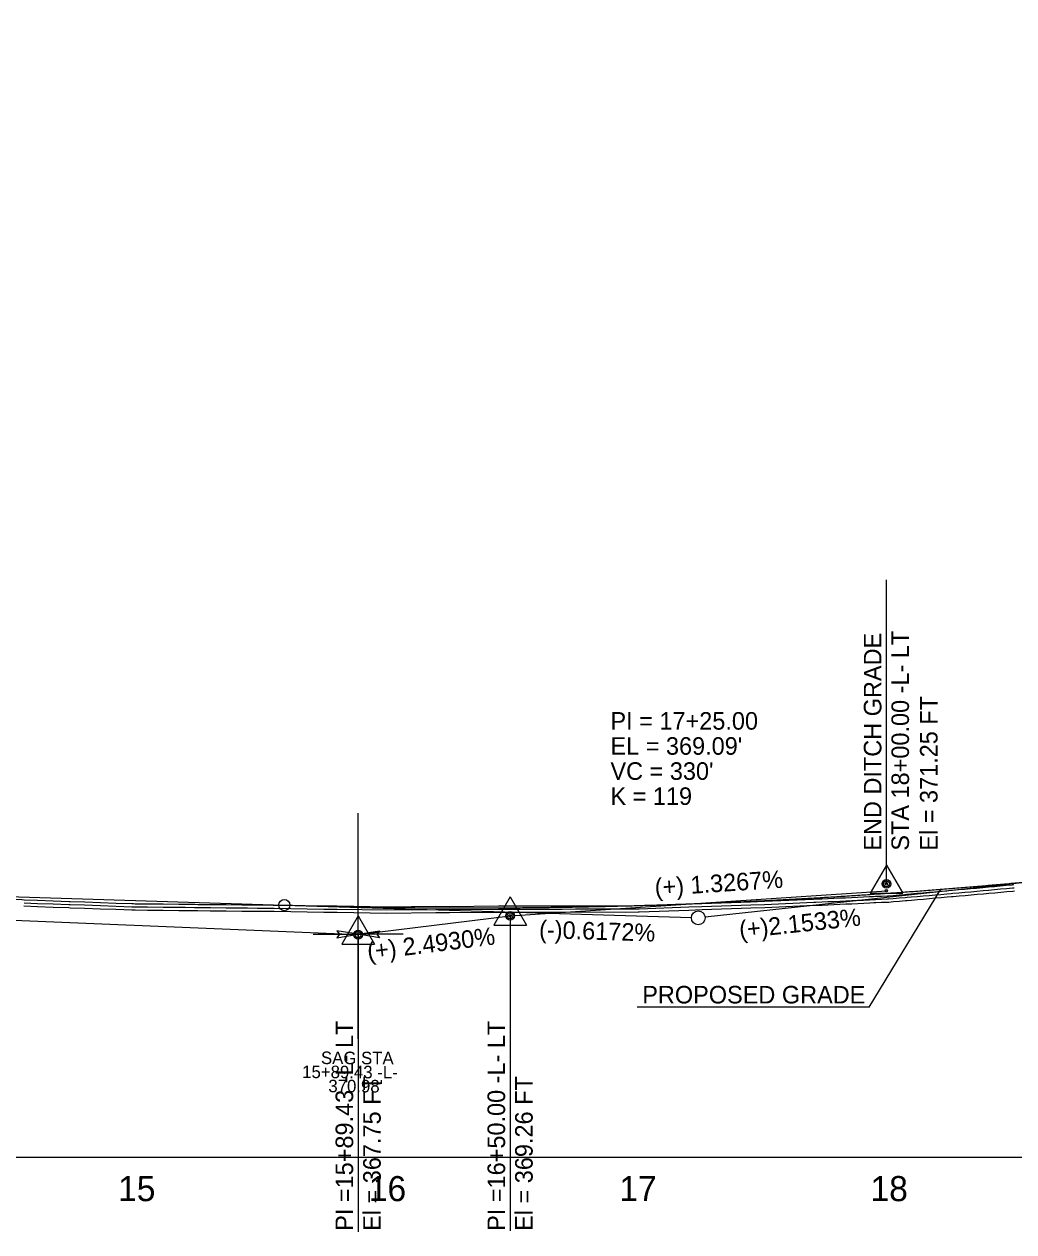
# Model space of a CAD drawing. Extents: x 1625686 to 1640492, y 1161393 to 1175642.
# Drawn here: x 1630660.6 to 1631055.1, y 1174881.1 to 1175362.5 of the extents above; entities that cross this region are included whole.
import ezdxf

# ---------------------------------------------------------------- set-up
doc = ezdxf.new("R2010")
doc.units = 0
for name, color, linetype in [('Exist Profile Cell', 7, 'Continuous'), ('Exist Vertical Profile Ground Line', 7, 'Continuous'), ('Exist Vertical Profile Horizontal Axis Label Major', 7, 'Continuous'), ('Prop Plan Preparation Sag', 7, 'Continuous'), ('Prop Vertical Profile Curve Label', 7, 'Continuous'), ('Prop Vertical Profile Ditch Grade Left', 7, 'Continuous'), ('Prop Vertical Profile Ditch Grade Left Label', 7, 'Continuous'), ('Prop Vertical Profile Grade', 7, 'Continuous'), ('Prop Vertical Profile Grade Label', 7, 'Continuous'), ('Prop VPI Ditch Grade Left Label', 7, 'Continuous'), ('Prop VPI Label', 7, 'Continuous'), ('Scratch_Level_1', 7, 'Continuous'), ('Scratch_Level_3', 7, 'Continuous'), ('Scratch_Level_5', 7, 'Continuous')]:
    doc.layers.add(name, color=color, linetype=linetype)

msp = doc.modelspace()

# ---------------------------------------------------------------- linework, layer by layer
at = {"layer": 'Exist Profile Cell'}
msp.add_line((1630204.31, 1174910.79), (1634670.63, 1174910.79), dxfattribs=at)
at = {"layer": 'Exist Vertical Profile Ground Line'}
msp.add_lwpolyline([(1630660.52, 1175010.95), (1630665.87, 1175010.76), (1630672.13, 1175010.53), (1630678.4, 1175010.3), (1630678.88, 1175010.28), (1630684.67, 1175010.1), (1630690.94, 1175009.87), (1630697.2, 1175009.64), (1630703.47, 1175009.42), (1630704.12, 1175009.39), (1630704.81, 1175009.37), (1630709.74, 1175009.32), (1630716.01, 1175009.26), (1630722.28, 1175009.2), (1630724.81, 1175009.18), (1630728.54, 1175009.13), (1630729.81, 1175009.11), (1630734.81, 1175009.06), (1630741.08, 1175009.01), (1630747.35, 1175008.95), (1630749.64, 1175008.94), (1630753.61, 1175008.88), (1630755.02, 1175008.86), (1630759.88, 1175008.83), (1630760.25, 1175008.83), (1630780.02, 1175008.49), (1630785.31, 1175008.46), (1630805.13, 1175008.13), (1630824.73, 1175008.32), (1630830.13, 1175008.3), (1630849.65, 1175008.49), (1630855.39, 1175008.48), (1630875.08, 1175008.47), (1630880.39, 1175008.56), (1630900.33, 1175008.55), (1630905.39, 1175008.63), (1630905.82, 1175008.63), (1630925.56, 1175009.31), (1630930.82, 1175009.49), (1630950.28, 1175010.17), (1630955.79, 1175010.35), (1630975.39, 1175011.22), (1630976.27, 1175011.25), (1630978.65, 1175011.34), (1630981.02, 1175011.43), (1630983.4, 1175011.54), (1630985.78, 1175011.65), (1630988.15, 1175011.76), (1630990.53, 1175011.87), (1630992.9, 1175011.98), (1630995.28, 1175012.09), (1630997.66, 1175012.21), (1630999.33, 1175012.29), (1631000.03, 1175012.32), (1631002.41, 1175012.42), (1631004.79, 1175012.52), (1631005.27, 1175012.54), (1631007.16, 1175012.7), (1631009.54, 1175012.9), (1631011.91, 1175013.1), (1631012.63, 1175013.16), (1631014.29, 1175013.31), (1631016.67, 1175013.51), (1631019.04, 1175013.72), (1631021.42, 1175013.93), (1631023.79, 1175014.14), (1631026.17, 1175014.35), (1631028.55, 1175014.56), (1631030.28, 1175014.71), (1631030.92, 1175014.77), (1631033.3, 1175014.98), (1631035.68, 1175015.19), (1631038.05, 1175015.4), (1631040.43, 1175015.62), (1631042.97, 1175015.85), (1631045.18, 1175016.05), (1631047.56, 1175016.26), (1631049.93, 1175016.48), (1631052.31, 1175016.7), (1631054.69, 1175016.92), (1631055.34, 1175016.98)], dxfattribs=at)
at = {"layer": 'Prop Plan Preparation Sag'}
for p, q in [((1630793.74, 1174957.96), (1630793.74, 1175047.91)), ((1630775.74, 1174999.68), (1630793.74, 1174999.68)), ((1630811.74, 1174999.68), (1630793.74, 1174999.68))]:
    msp.add_line(p, q, dxfattribs=at)
for points in [[(1630785.18, 1174998.25), (1630793.74, 1174999.68), (1630785.18, 1175001.1), (1630786.24, 1174999.68)], [(1630802.31, 1174998.25), (1630793.74, 1174999.68), (1630802.31, 1175001.1), (1630801.24, 1174999.68)]]:
    msp.add_lwpolyline(points, close=True, dxfattribs=at)
at = {"layer": 'Prop Vertical Profile Curve Label'}
msp.add_circle((1630764.31, 1175011.33), 2.25, dxfattribs=at)
at = {"layer": 'Prop Vertical Profile Ditch Grade Left'}
msp.add_lwpolyline([(1630254.31, 1175022.04), (1630793.74, 1174999.54), (1630854.31, 1175007.09), (1631004.31, 1175017.04)], dxfattribs=at)
msp.add_circle((1631004.31, 1175019.79), 0.5, dxfattribs=at)
at = {"layer": 'Prop Vertical Profile Grade'}
msp.add_line((1630608.23, 1175016.14), (1630764.31, 1175011.33), dxfattribs=at)
msp.add_spline([(1630764.31, 1175011.33), (1630770.91, 1175011.13), (1630777.51, 1175010.96), (1630784.11, 1175010.8), (1630790.71, 1175010.66), (1630797.31, 1175010.54), (1630803.91, 1175010.44), (1630810.51, 1175010.35), (1630817.11, 1175010.28), (1630823.71, 1175010.24), (1630830.31, 1175010.21), (1630836.91, 1175010.19), (1630843.51, 1175010.2), (1630850.11, 1175010.23), (1630856.71, 1175010.27), (1630863.31, 1175010.33), (1630869.91, 1175010.41), (1630876.51, 1175010.51), (1630883.11, 1175010.62), (1630889.71, 1175010.76), (1630896.31, 1175010.91), (1630902.91, 1175011.08), (1630909.51, 1175011.27), (1630916.11, 1175011.48), (1630922.71, 1175011.71), (1630929.31, 1175011.95), (1630935.91, 1175012.21), (1630942.51, 1175012.49), (1630949.11, 1175012.79), (1630955.71, 1175013.11), (1630962.31, 1175013.45), (1630968.91, 1175013.8), (1630975.51, 1175014.17), (1630982.11, 1175014.56), (1630988.71, 1175014.97), (1630995.31, 1175015.4), (1631001.91, 1175015.85), (1631008.51, 1175016.31), (1631015.11, 1175016.79), (1631021.71, 1175017.29), (1631028.31, 1175017.81), (1631034.91, 1175018.35), (1631041.51, 1175018.9), (1631048.11, 1175019.48), (1631054.71, 1175020.07), (1631061.31, 1175020.68), (1631067.91, 1175021.31), (1631074.51, 1175021.95), (1631081.11, 1175022.62), (1631087.71, 1175023.3), (1631094.31, 1175024)], degree=3, dxfattribs=at)
at = {"layer": 'Prop VPI Ditch Grade Left Label'}
for p, q in [((1631004.31, 1175019.79), (1631004.31, 1175141.01)), ((1631004.31, 1175027.27), (1630997.86, 1175016.07)), ((1631004.31, 1175027.27), (1631010.81, 1175016.07)), ((1630854.31, 1175014.55), (1630847.86, 1175003.35)), ((1630854.31, 1175014.55), (1630860.81, 1175003.35)), ((1630997.86, 1175016.07), (1631010.81, 1175016.07)), ((1630793.74, 1175007), (1630787.29, 1174995.8)), ((1630793.74, 1175007), (1630800.24, 1174995.8)), ((1630847.86, 1175003.35), (1630860.81, 1175003.35)), ((1630854.31, 1175007.09), (1630854.31, 1174881.45)), ((1630793.74, 1174999.52), (1630793.74, 1174881.06)), ((1630787.29, 1174995.8), (1630800.24, 1174995.8))]:
    msp.add_line(p, q, dxfattribs=at)
for centre, radius in [((1631004.31, 1175019.79), 1.75), ((1631004.31, 1175019.79), 1.2), ((1631004.31, 1175019.79), 0.5), ((1631004.31, 1175019.79), 0.5), ((1631004.31, 1175017.04), 0.5), ((1630854.31, 1175007.07), 1.75), ((1630854.31, 1175007.07), 1.2), ((1630854.31, 1175007.09), 0.5), ((1630793.74, 1174999.52), 1.75), ((1630793.74, 1174999.52), 1.2)]:
    msp.add_circle(centre, radius, dxfattribs=at)
at = {"layer": 'Prop VPI Label'}
for p, q in [((1631094.31, 1175024), (1630932.05, 1175006.53)), ((1630997.48, 1174970.66), (1631025.95, 1175017.62)), ((1630764.31, 1175011.33), (1630926.57, 1175006.32)), ((1630997.48, 1174970.66), (1630904.93, 1174970.66))]:
    msp.add_line(p, q, dxfattribs=at)
msp.add_circle((1630929.31, 1175006.24), 2.75, dxfattribs=at)
at = {"layer": 'Scratch_Level_1'}
for p, q in [((1630749.66, 1175010.19), (1630753.63, 1175010.13)), ((1630749.67, 1175011.44), (1630753.65, 1175011.38))]:
    msp.add_line(p, q, dxfattribs=at)
for points in [[(1630999.22, 1175014.79), (1630999.93, 1175014.82), (1631002.3, 1175014.92), (1631004.68, 1175015.02), (1631005.12, 1175015.03), (1631006.95, 1175015.19), (1631009.33, 1175015.39), (1631011.7, 1175015.59), (1631012.41, 1175015.66), (1631014.08, 1175015.8), (1631016.45, 1175016), (1631018.83, 1175016.21), (1631021.2, 1175016.42), (1631023.58, 1175016.63), (1631025.95, 1175016.84), (1631028.33, 1175017.05), (1631030.06, 1175017.2)], [(1631030.06, 1175017.2), (1631030.7, 1175017.26), (1631033.08, 1175017.47), (1631035.45, 1175017.68), (1631037.83, 1175017.89), (1631040.2, 1175018.11), (1631042.74, 1175018.34), (1631044.95, 1175018.54), (1631047.33, 1175018.75), (1631049.7, 1175018.97), (1631052.08, 1175019.19), (1631054.45, 1175019.41), (1631055.1, 1175019.47)], [(1631030.17, 1175015.95), (1631030.81, 1175016.01), (1631033.19, 1175016.22), (1631035.56, 1175016.43), (1631037.94, 1175016.65), (1631040.32, 1175016.86), (1631042.85, 1175017.09), (1631045.07, 1175017.29), (1631047.44, 1175017.51), (1631049.82, 1175017.73), (1631052.19, 1175017.95), (1631054.57, 1175018.17), (1631055.22, 1175018.23)], [(1630629.64, 1175014.86), (1630634.65, 1175014.61), (1630637.28, 1175014.47), (1630640.92, 1175014.3), (1630647.18, 1175013.99), (1630653.45, 1175013.69), (1630653.97, 1175013.66), (1630659.68, 1175013.48), (1630660.6, 1175013.45)], [(1630660.57, 1175012.2), (1630665.91, 1175012), (1630672.18, 1175011.78), (1630678.45, 1175011.55), (1630678.92, 1175011.53), (1630684.71, 1175011.35)], [(1630660.61, 1175013.45), (1630665.96, 1175013.25), (1630672.22, 1175013.02), (1630678.49, 1175012.8), (1630678.97, 1175012.78), (1630684.75, 1175012.6)], [(1630684.76, 1175012.6), (1630691.03, 1175012.37), (1630697.3, 1175012.14), (1630703.56, 1175011.91), (1630704.21, 1175011.89)], [(1630925.48, 1175011.81), (1630930.73, 1175011.99), (1630950.19, 1175012.66)], [(1630950.19, 1175012.66), (1630955.7, 1175012.85), (1630975.28, 1175013.72)], [(1630950.24, 1175011.41), (1630955.75, 1175011.6), (1630975.33, 1175012.47)], [(1630975.29, 1175013.72), (1630976.18, 1175013.75), (1630978.55, 1175013.84), (1630980.92, 1175013.93), (1630983.29, 1175014.04), (1630985.66, 1175014.15), (1630988.04, 1175014.26), (1630990.41, 1175014.37), (1630992.79, 1175014.48), (1630995.16, 1175014.59), (1630997.54, 1175014.7), (1630999.21, 1175014.79)], [(1630975.34, 1175012.47), (1630976.22, 1175012.5), (1630978.6, 1175012.59), (1630980.97, 1175012.68), (1630983.34, 1175012.79), (1630985.72, 1175012.9), (1630988.09, 1175013.01), (1630990.47, 1175013.12), (1630992.85, 1175013.23), (1630995.22, 1175013.34), (1630997.6, 1175013.46), (1630999.27, 1175013.54)], [(1630999.28, 1175013.54), (1630999.98, 1175013.57), (1631002.36, 1175013.67), (1631004.73, 1175013.77), (1631005.2, 1175013.79), (1631007.06, 1175013.94), (1631009.43, 1175014.15), (1631011.81, 1175014.35), (1631012.52, 1175014.41), (1631014.18, 1175014.55), (1631016.56, 1175014.76), (1631018.93, 1175014.97), (1631021.31, 1175015.17), (1631023.69, 1175015.38), (1631026.06, 1175015.59), (1631028.44, 1175015.8), (1631030.17, 1175015.95)], [(1630684.71, 1175011.35), (1630690.98, 1175011.12), (1630697.25, 1175010.89), (1630703.52, 1175010.66), (1630704.17, 1175010.64)], [(1630704.17, 1175010.64), (1630704.84, 1175010.62), (1630709.75, 1175010.57), (1630716.02, 1175010.51), (1630722.29, 1175010.45), (1630724.82, 1175010.43)], [(1630704.21, 1175011.89), (1630704.87, 1175011.87), (1630709.76, 1175011.82), (1630716.03, 1175011.76), (1630722.3, 1175011.7), (1630724.83, 1175011.68)], [(1630724.83, 1175010.43), (1630728.56, 1175010.38), (1630729.83, 1175010.36), (1630734.82, 1175010.31), (1630741.09, 1175010.26), (1630747.36, 1175010.2), (1630749.65, 1175010.19)], [(1630724.85, 1175011.68), (1630728.58, 1175011.63), (1630729.84, 1175011.61), (1630734.83, 1175011.56), (1630741.1, 1175011.51), (1630747.37, 1175011.45), (1630749.66, 1175011.44)], [(1630753.63, 1175010.13), (1630755.03, 1175010.11), (1630759.89, 1175010.08), (1630760.25, 1175010.08)], [(1630753.65, 1175011.38), (1630755.05, 1175011.36), (1630759.9, 1175011.33), (1630760.26, 1175011.33)], [(1630760.27, 1175010.08), (1630780.04, 1175009.74), (1630785.32, 1175009.71)], [(1630760.29, 1175011.33), (1630780.05, 1175010.99), (1630785.32, 1175010.96)], [(1630785.33, 1175009.71), (1630805.13, 1175009.38), (1630824.72, 1175009.57)], [(1630785.35, 1175010.96), (1630805.14, 1175010.63), (1630824.71, 1175010.82)], [(1630824.74, 1175010.82), (1630830.12, 1175010.8), (1630849.62, 1175010.99)], [(1630824.74, 1175009.57), (1630830.12, 1175009.55), (1630849.64, 1175009.74)], [(1630849.65, 1175009.74), (1630855.39, 1175009.73), (1630875.07, 1175009.72), (1630880.37, 1175009.81)], [(1630849.66, 1175010.99), (1630855.39, 1175010.98), (1630875.06, 1175010.97), (1630880.35, 1175011.06)], [(1630880.39, 1175011.06), (1630900.31, 1175011.05), (1630905.35, 1175011.13)], [(1630880.39, 1175009.81), (1630900.32, 1175009.8), (1630905.37, 1175009.88)], [(1630905.38, 1175011.13), (1630905.77, 1175011.13), (1630925.48, 1175011.81)], [(1630905.38, 1175009.88), (1630905.8, 1175009.88), (1630925.52, 1175010.56)], [(1630925.52, 1175010.56), (1630930.78, 1175010.74), (1630950.24, 1175011.41)]]:
    msp.add_lwpolyline(points, dxfattribs=at)
for centre, radius, start, end in [((1631030.28, 1175014.71), 2.5, 95.0539, 95.0764), ((1631055.34, 1175016.98), 2.5, 95.2304, 95.3055), ((1630660.52, 1175010.95), 2.5, 87.9027, 88.1863), ((1630684.67, 1175010.1), 2.5, 87.9096, 88.1967), ((1630950.28, 1175010.17), 2.5, 91.9676, 91.9796), ((1630975.39, 1175011.22), 2.5, 92.155, 92.5215), ((1630975.39, 1175011.22), 1.25, 92.155, 92.5215), ((1630999.33, 1175012.29), 2.5, 92.384, 92.7672), ((1630999.33, 1175012.29), 1.25, 92.384, 92.7672), ((1631030.28, 1175014.71), 1.25, 95.0539, 95.0764), ((1630684.67, 1175010.1), 1.25, 87.9096, 88.1967), ((1630704.12, 1175009.39), 1.25, 87.9626, 88.0297), ((1630704.12, 1175009.39), 2.5, 87.9626, 88.0297), ((1630724.81, 1175009.18), 1.25, 89.1584, 89.4767), ((1630724.81, 1175009.18), 2.5, 89.1584, 89.4767), ((1630749.64, 1175008.94), 1.25, 89.179, 89.5149), ((1630749.64, 1175008.94), 2.5, 89.179, 89.5149), ((1630753.61, 1175008.88), 1.25, 89.1602, 89.179), ((1630753.61, 1175008.88), 2.5, 89.1602, 89.179), ((1630760.25, 1175008.83), 1.25, 89.0228, 89.6776), ((1630760.25, 1175008.83), 2.5, 89.0228, 89.6776), ((1630785.31, 1175008.46), 2.5, 89.0303, 89.6771), ((1630785.31, 1175008.46), 1.25, 89.0303, 89.6771), ((1630824.73, 1175008.32), 2.5, 89.8009, 90.568), ((1630824.73, 1175008.32), 1.25, 89.8009, 90.568), ((1630849.65, 1175008.49), 2.5, 89.8321, 90.5662), ((1630849.65, 1175008.49), 1.25, 89.8321, 90.5662), ((1630880.39, 1175008.56), 2.5, 89.9846, 90.9026), ((1630880.39, 1175008.56), 1.25, 89.9846, 90.9026), ((1630905.39, 1175008.63), 2.5, 90.2212, 90.8972), ((1630905.39, 1175008.63), 1.25, 90.2212, 90.8972), ((1630925.56, 1175009.31), 2.5, 91.9708, 91.976), ((1630925.56, 1175009.31), 1.25, 91.9708, 91.976), ((1630950.28, 1175010.17), 1.25, 91.9676, 91.9796)]:
    msp.add_arc(centre, radius, start, end, dxfattribs=at)
at = {"layer": 'Scratch_Level_3'}
msp.add_lwpolyline([(1630204.31, 1174910.79), (1634341.72, 1174910.79), (1634341.72, 1175362.47)], dxfattribs=at)
at = {"layer": 'Scratch_Level_5'}
msp.add_lwpolyline([(1630660.52, 1175010.95), (1630665.87, 1175010.76), (1630672.13, 1175010.53), (1630678.4, 1175010.3), (1630678.88, 1175010.28), (1630684.67, 1175010.1), (1630690.94, 1175009.87), (1630697.2, 1175009.64), (1630703.47, 1175009.42), (1630704.12, 1175009.39), (1630704.81, 1175009.37), (1630709.74, 1175009.32), (1630716.01, 1175009.26), (1630722.28, 1175009.2), (1630724.81, 1175009.18), (1630728.54, 1175009.13), (1630729.81, 1175009.11), (1630734.81, 1175009.06), (1630741.08, 1175009.01), (1630747.35, 1175008.95), (1630749.64, 1175008.94), (1630753.61, 1175008.88), (1630755.02, 1175008.86), (1630759.88, 1175008.83), (1630760.25, 1175008.83), (1630780.02, 1175008.49), (1630785.31, 1175008.46), (1630805.13, 1175008.13), (1630824.73, 1175008.32), (1630830.13, 1175008.3), (1630849.65, 1175008.49), (1630855.39, 1175008.48), (1630875.08, 1175008.47), (1630880.39, 1175008.56), (1630900.33, 1175008.55), (1630905.39, 1175008.63), (1630905.82, 1175008.63), (1630925.56, 1175009.31), (1630930.82, 1175009.49), (1630950.28, 1175010.17), (1630955.79, 1175010.35), (1630975.39, 1175011.22), (1630976.27, 1175011.25), (1630978.65, 1175011.34), (1630981.02, 1175011.43), (1630983.4, 1175011.54), (1630985.78, 1175011.65), (1630988.15, 1175011.76), (1630990.53, 1175011.87), (1630992.9, 1175011.98), (1630995.28, 1175012.09), (1630997.66, 1175012.21), (1630999.33, 1175012.29), (1631000.03, 1175012.32), (1631002.41, 1175012.42), (1631004.79, 1175012.52), (1631005.27, 1175012.54), (1631007.16, 1175012.7), (1631009.54, 1175012.9), (1631011.91, 1175013.1), (1631012.63, 1175013.16), (1631014.29, 1175013.31), (1631016.67, 1175013.51), (1631019.04, 1175013.72), (1631021.42, 1175013.93), (1631023.79, 1175014.14), (1631026.17, 1175014.35), (1631028.55, 1175014.56), (1631030.28, 1175014.71), (1631030.92, 1175014.77), (1631033.3, 1175014.98), (1631035.68, 1175015.19), (1631038.05, 1175015.4), (1631040.43, 1175015.62), (1631042.97, 1175015.85), (1631045.18, 1175016.05), (1631047.56, 1175016.26), (1631049.93, 1175016.48), (1631052.31, 1175016.7), (1631054.69, 1175016.92), (1631055.34, 1175016.98)], dxfattribs=at)

# ---------------------------------------------------------------- texts
at = {"layer": 'Exist Vertical Profile Horizontal Axis Label Major'}
for s, p in [('15', (1630698.05, 1174893.29)), ('16', (1630798, 1174893.29)), ('17', (1630897.85, 1174893.29)), ('18', (1630997.98, 1174893.29))]:
    msp.add_text(s, height=10, dxfattribs=at).set_placement(p)
at = {"layer": 'Prop Plan Preparation Sag'}
for s, p in [('SAG STA', (1630778.91, 1174947.94)), ('15+89.43 -L-', (1630771.42, 1174942.36)), ("370.98'", (1630781.85, 1174936.71))]:
    msp.add_text(s, height=5, rotation=359.7547, dxfattribs=at).set_placement(p)
at = {"layer": 'Prop Vertical Profile Curve Label'}
for s, p in [("VC = 330'", (1630894.31, 1175061.24)), ('K = 119', (1630894.31, 1175051.24))]:
    msp.add_text(s, height=7, dxfattribs=at).set_placement(p)
at = {"layer": 'Prop Vertical Profile Ditch Grade Left Label'}
for s, rotation, p in [('(+) 1.3267%', 3.7951, (1630912.17, 1175014.86)), ('(+) 2.4930%', 7.1052, (1630797.79, 1174989.32))]:
    msp.add_text(s, height=7, rotation=rotation, dxfattribs=at).set_placement(p)
at = {"layer": 'Prop Vertical Profile Grade Label'}
for s, rotation, p in [('(+)2.1533%', 6.1452, (1630945.99, 1174997.97)), ('(-)0.6172%', 358.2325, (1630865.78, 1174998.19))]:
    msp.add_text(s, height=7, rotation=rotation, dxfattribs=at).set_placement(p)
at = {"layer": 'Prop VPI Ditch Grade Left Label'}
for s, p in [('END DITCH GRADE', (1631002.31, 1175033)), ('STA 18+00.00 -L- LT', (1631013.31, 1175033)), ('El = 371.25 FT', (1631024.69, 1175033)), ('PI =15+89.43 -L- LT', (1630791.74, 1174881.46)), ('PI =16+50.00 -L- LT', (1630852.31, 1174881.45)), ('El = 367.75 FT', (1630802.74, 1174881.46)), ('El = 369.26 FT', (1630863.31, 1174881.45))]:
    msp.add_text(s, height=7, rotation=90, dxfattribs=at).set_placement(p)
at = {"layer": 'Prop VPI Label'}
for s, p in [('PI = 17+25.00', (1630894.31, 1175081.24)), ("EL = 369.09'", (1630894.31, 1175071.24)), ('PROPOSED GRADE', (1630906.98, 1174972.1))]:
    msp.add_text(s, height=7, dxfattribs=at).set_placement(p)

doc.saveas('drawing.dxf')
